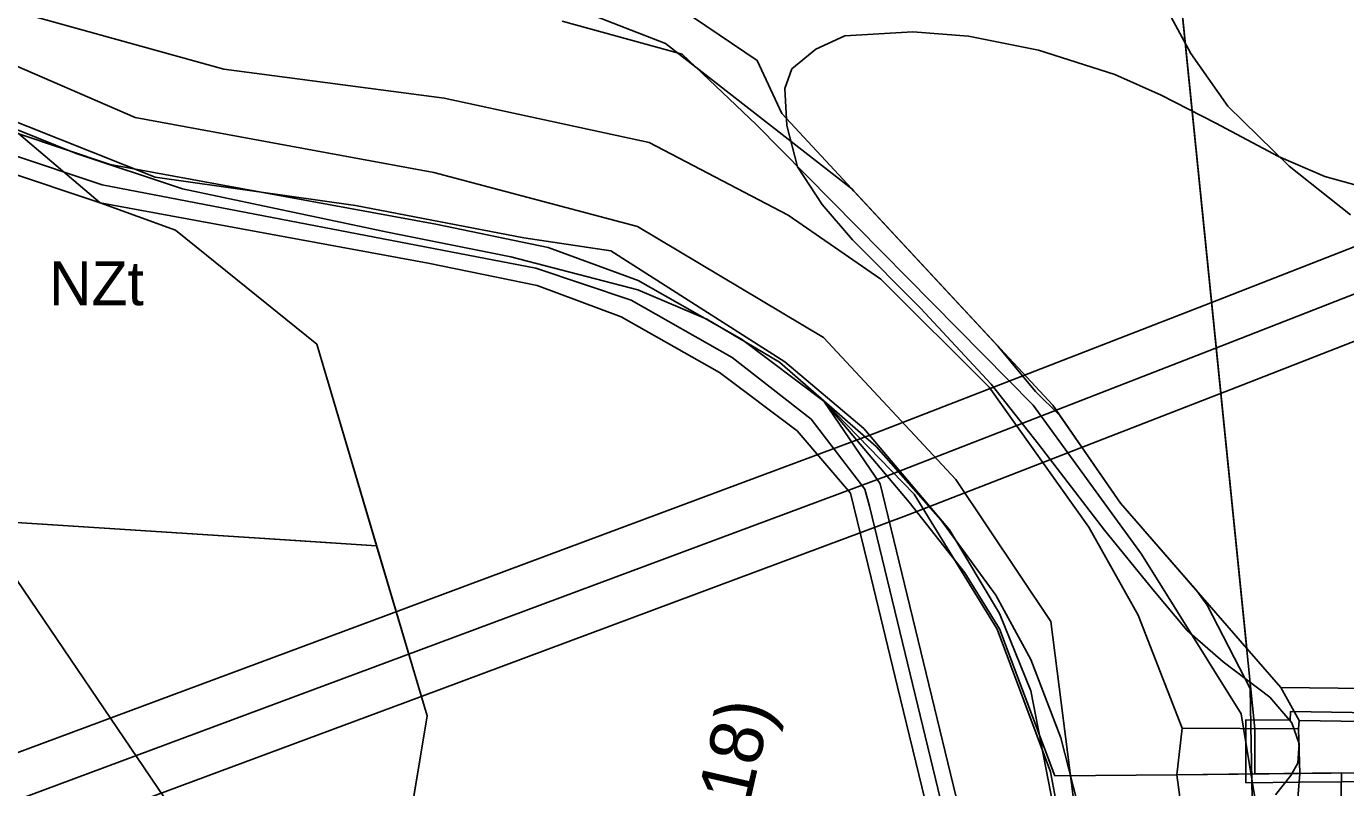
# Model space of a CAD drawing. Extents: x -758499 to -754160, y -1175205 to -1172032.
# Drawn here: x -756363 to -756063.4, y -1173393.7 to -1173220.7 of the extents above; entities that cross this region are included whole.
import ezdxf

# ---------------------------------------------------------------- set-up
doc = ezdxf.new("R2010")
doc.units = 0
for name, color, linetype in [('A012_RegLidArch_p', 7, 'Continuous'), ('A041_BPEJ_p', 7, 'Continuous'), ('A043_InvPuda_p', 7, 'Continuous'), ('A073_ElVed_l_VN', 7, 'Continuous'), ('A073_ElVed_op', 7, 'Continuous'), ('D cyklocesty NÁVRH', 7, 'Continuous'), ('HRANICE změn v krajině', 7, 'Continuous'), ('indexy RZV_TYP_1', 7, 'Continuous'), ('NÁVRH NZt zeměděl-trvalý travní porost', 7, 'Continuous'), ('PLOCHY NS smíšené nezastavěného území', 7, 'Continuous'), ('PLOCHY NZo zemědělské-orná půda', 7, 'Continuous'), ('PLOCHY NZt zeměděl-trvalý travní porost', 7, 'Continuous'), ('PLOCHY PV prostranství veřejné', 7, 'Continuous'), ('PLOCHY VV vodní a vodohospodářské', 7, 'Continuous'), ('vrstevnice', 7, 'Continuous'), ('ÚSES interakční prvek', 7, 'Continuous'), ('ÚSES LBC jako součást RBK', 7, 'Continuous'), ('ÚSES NBK funkční', 7, 'Continuous')]:
    doc.layers.add(name, color=color, linetype=linetype)

msp = doc.modelspace()

# ---------------------------------------------------------------- linework, layer by layer
at = {"layer": 'A012_RegLidArch_p'}
for p, q in [((-756394.8, -1173216.86), (-756338.3, -1173241.39)), ((-756338.3, -1173241.39), (-756270.44, -1173253.88)), ((-756270.44, -1173253.88), (-756224.2, -1173266.16)), ((-756224.2, -1173266.16), (-756182, -1173291.38)), ((-756182, -1173291.38), (-756151.93, -1173323.65)), ((-756151.93, -1173323.65), (-756130.31, -1173355.91)), ((-756130.31, -1173355.91), (-756120.85, -1173430.13))]:
    msp.add_line(p, q, dxfattribs=at)
at = {"layer": 'A041_BPEJ_p'}
for p, q in [((-756109.47, -1173206.48), (-756098.56, -1173226.87)), ((-756098.56, -1173226.87), (-756109.47, -1173206.48)), ((-756241.66, -1173215.35), (-756217.82, -1173224.56)), ((-756217.82, -1173224.56), (-756241.66, -1173215.35)), ((-756217.82, -1173224.56), (-756175.55, -1173257.62)), ((-756175.55, -1173257.62), (-756217.82, -1173224.56)), ((-756098.56, -1173226.87), (-756090.14, -1173238.78)), ((-756090.14, -1173238.78), (-756098.56, -1173226.87)), ((-756393.93, -1173231.07), (-756333.78, -1173254.91)), ((-756333.78, -1173254.91), (-756393.93, -1173231.07)), ((-756090.14, -1173238.78), (-756076.22, -1173252.42)), ((-756076.22, -1173252.42), (-756090.14, -1173238.78)), ((-756076.22, -1173252.42), (-756062.29, -1173263.52)), ((-756062.29, -1173263.52), (-756076.22, -1173252.42)), ((-756333.78, -1173254.91), (-756288.27, -1173261.41)), ((-756288.27, -1173261.41), (-756333.78, -1173254.91)), ((-756175.55, -1173257.62), (-756175.06, -1173258.13)), ((-756175.06, -1173258.13), (-756175.55, -1173257.62)), ((-756175.06, -1173258.13), (-756142.26, -1173293.45)), ((-756142.26, -1173293.45), (-756175.06, -1173258.13)), ((-756288.27, -1173261.41), (-756250, -1173268.73)), ((-756250, -1173268.73), (-756288.27, -1173261.41)), ((-756250, -1173268.73), (-756230.28, -1173271.71)), ((-756230.28, -1173271.71), (-756250, -1173268.73)), ((-756230.28, -1173271.71), (-756190.73, -1173296.9)), ((-756190.73, -1173296.9), (-756230.28, -1173271.71)), ((-756142.26, -1173293.45), (-756133.83, -1173303.68)), ((-756133.83, -1173303.68), (-756142.26, -1173293.45)), ((-756190.73, -1173296.9), (-756172.84, -1173312.08)), ((-756172.84, -1173312.08), (-756190.73, -1173296.9)), ((-756133.83, -1173303.68), (-756128.27, -1173309.11)), ((-756128.27, -1173309.11), (-756133.83, -1173303.68)), ((-756128.27, -1173309.11), (-756114.52, -1173329.01)), ((-756114.52, -1173329.01), (-756128.27, -1173309.11)), ((-756172.84, -1173312.08), (-756153.34, -1173335.11)), ((-756153.34, -1173335.11), (-756172.84, -1173312.08)), ((-756114.52, -1173329.01), (-756097.16, -1173348.97)), ((-756097.16, -1173348.97), (-756114.52, -1173329.01)), ((-756153.34, -1173335.11), (-756141.96, -1173354.07)), ((-756141.96, -1173354.07), (-756153.34, -1173335.11)), ((-756097.16, -1173348.97), (-756094.81, -1173352.18)), ((-756094.81, -1173352.18), (-756097.16, -1173348.97)), ((-756094.81, -1173352.18), (-756085.06, -1173371.14)), ((-756085.06, -1173371.14), (-756094.81, -1173352.18)), ((-756141.96, -1173354.07), (-756134.91, -1173371.68)), ((-756134.91, -1173371.68), (-756141.96, -1173354.07)), ((-756134.91, -1173371.68), (-756127.05, -1173411.78)), ((-756127.05, -1173411.78), (-756134.91, -1173371.68)), ((-756085.06, -1173371.14), (-756083.97, -1173428.85)), ((-756083.97, -1173428.85), (-756085.06, -1173371.14))]:
    msp.add_line(p, q, dxfattribs=at)
at = {"layer": 'A043_InvPuda_p'}
msp.add_line((-756482.65, -1173173.48), (-756302.97, -1173438.22), dxfattribs=at)
at = {"layer": 'A073_ElVed_l_VN'}
msp.add_lwpolyline([(-755889.67, -1173214.41), (-755997.14, -1173256.36), (-756090.37, -1173292.81), (-756166.71, -1173322.49), (-756277.23, -1173363.71), (-756391.79, -1173406.32), (-756503.08, -1173447.76), (-756614.81, -1173489.45), (-756725.9, -1173530.87), (-756829.91, -1173569.83)], dxfattribs=at)
at = {"layer": 'A073_ElVed_op'}
for points in [[(-756937.08, -1173599.18), (-756833.41, -1173560.46), (-756729.4, -1173521.5), (-756618.3, -1173480.08), (-756506.57, -1173438.39), (-756395.28, -1173396.95), (-756280.72, -1173354.34), (-756170.27, -1173313.14), (-756094, -1173283.49), (-756000.78, -1173247.05), (-755893.3, -1173205.09), (-755782.45, -1173161.86), (-755672.55, -1173119.02), (-755584.87, -1173084.82), (-755525.32, -1173086.94), (-755455.27, -1173089.86)], [(-755445.09, -1173111.7), (-755451.32, -1173110.05), (-755526.1, -1173106.92), (-755581.45, -1173104.96), (-755665.29, -1173137.66), (-755775.19, -1173180.5), (-755886.04, -1173223.73), (-755993.5, -1173265.67), (-756086.74, -1173302.13), (-756163.15, -1173331.84), (-756273.74, -1173373.08), (-756388.3, -1173415.69), (-756499.59, -1173457.13), (-756611.32, -1173498.82), (-756722.4, -1173540.24), (-756826.41, -1173579.2), (-756944.42, -1173623.27), (-756946.15, -1173623.58)]]:
    msp.add_lwpolyline(points, dxfattribs=at)
at = {"layer": 'D cyklocesty NÁVRH'}
for points in [[(-756433.17, -1173211.78), (-756414.04, -1173225.98), (-756390.12, -1173239.24), (-756366.64, -1173249.68), (-756345.77, -1173256.71), (-756247.28, -1173275.63), (-756225.64, -1173282.91), (-756202.74, -1173295.95), (-756184.77, -1173309.94), (-756172.56, -1173325.85), (-756171.51, -1173329.73), (-756155.38, -1173396.37), (-756155.96, -1173403.47), (-756162.92, -1173417.39), (-756161.76, -1173444.93), (-756154.08, -1173473.63), (-756147.12, -1173494.06), (-756148.28, -1173501.6), (-756152.48, -1173511.53), (-756169.15, -1173538.78), (-756182.2, -1173559.07), (-756209.01, -1173591.54), (-756236.26, -1173624.44)], [(-756249.6, -1173995.8), (-756304.39, -1173806.64), (-756305.26, -1173790.41), (-756304.1, -1173771.42), (-756294.53, -1173742.29), (-756274.67, -1173711.7), (-756265.69, -1173702.57), (-756213.5, -1173657.2), (-756173.79, -1173608.93), (-756149, -1173575.45), (-756123.93, -1173539.07), (-756113.78, -1173523.85), (-756096.39, -1173481.53), (-756089.28, -1173456.16), (-756083.34, -1173400.06), (-756087.11, -1173376.87), (-756109.72, -1173340.64), (-756134.36, -1173306.72), (-756197.27, -1173242.94), (-756214.08, -1173227), (-756241.33, -1173219.46)]]:
    msp.add_lwpolyline(points, dxfattribs=at)
at = {"layer": 'HRANICE změn v krajině'}
for points in [[(-756109.32, -1173130.91), (-756085.79, -1173362.04), (-756114.52, -1173329.01), (-756129.9, -1173306.76), (-756191.42, -1173240.51), (-756197.01, -1173228.43), (-756211.53, -1173218.65)], [(-756295.76, -1173521.24), (-756272, -1173377.37), (-756283.48, -1173338.71), (-756297.08, -1173292.89), (-756329.16, -1173266.98), (-756346.27, -1173260.76), (-756271.77, -1173274.48), (-756247.02, -1173279.58), (-756227.9, -1173286.65), (-756205.57, -1173299.31), (-756187.95, -1173312.56), (-756175.8, -1173326.75), (-756171.13, -1173345.99), (-756165.13, -1173370.73), (-756158.94, -1173396.25)]]:
    msp.add_lwpolyline(points, dxfattribs=at)
at = {"layer": 'NÁVRH NZt zeměděl-trvalý travní porost'}
for points in [[(-756109.32, -1173130.91), (-756085.79, -1173362.04), (-756114.52, -1173329.01), (-756129.9, -1173306.76), (-756191.42, -1173240.51), (-756197.01, -1173228.43), (-756211.53, -1173218.65)], [(-756295.76, -1173521.24), (-756272, -1173377.37), (-756283.48, -1173338.71), (-756297.08, -1173292.89), (-756329.16, -1173266.98), (-756346.27, -1173260.76), (-756271.77, -1173274.48), (-756247.02, -1173279.58), (-756227.9, -1173286.65), (-756205.57, -1173299.31), (-756187.95, -1173312.56), (-756175.8, -1173326.75), (-756171.13, -1173345.99), (-756165.13, -1173370.73), (-756158.94, -1173396.25)]]:
    msp.add_lwpolyline(points, dxfattribs=at)
at = {"layer": 'PLOCHY NS smíšené nezastavěného území'}
for points in [[(-756181.93, -1173305.82), (-756161.35, -1173326.95), (-756142.53, -1173357.66), (-756130.38, -1173390.03), (-756127.49, -1173405.81), (-756127.1, -1173440.75), (-756132.49, -1173472.62), (-756141.86, -1173497.39), (-756150.45, -1173474.34), (-756158.33, -1173444.24), (-756159.88, -1173418.2), (-756150.62, -1173400.84), (-756169.11, -1173324.64)], [(-756078.11, -1173370.87), (-755954.66, -1173372.32), (-755894.6, -1173371.63), (-755787.2, -1173371.96), (-755762.88, -1173369.67), (-755764.66, -1173377.87), (-755786.84, -1173379.96), (-755894.57, -1173379.63), (-755954.68, -1173380.32), (-756073.97, -1173378.42)], [(-756073.75, -1173390.42), (-755952.64, -1173389.17), (-755765.3, -1173388.97), (-755768.56, -1173394.97), (-755781.33, -1173395.88), (-755908.85, -1173395.64), (-755955.98, -1173396.49), (-756056.15, -1173398.03), (-756074.52, -1173399.82)]]:
    msp.add_lwpolyline(points, close=True, dxfattribs=at)
at = {"layer": 'PLOCHY NZo zemědělské-orná půda'}
for points in [[(-755723.48, -1173177.46), (-755733.96, -1173231.89), (-755736.18, -1173243.56), (-755741.53, -1173271.48), (-755752.03, -1173322.1), (-755758.93, -1173351.52), (-755762.88, -1173369.67), (-755787.2, -1173371.96), (-755894.6, -1173371.63), (-755954.66, -1173372.32), (-756078.11, -1173370.87), (-756085.79, -1173362.04), (-756109.32, -1173130.91)], [(-756439.98, -1173212.39), (-756430.37, -1173222.44), (-756432.3, -1173329.06), (-756311.31, -1173336.9), (-756283.48, -1173338.71), (-756272, -1173377.37), (-756295.76, -1173521.24), (-756415.28, -1173701.51), (-756445.99, -1173697.96)]]:
    msp.add_lwpolyline(points, dxfattribs=at)
at = {"layer": 'PLOCHY NZt zeměděl-trvalý travní porost'}
msp.add_lwpolyline([(-756430.37, -1173222.44), (-756393.84, -1173242.18), (-756367.97, -1173253.52), (-756346.27, -1173260.76), (-756329.16, -1173266.98), (-756297.08, -1173292.89), (-756283.48, -1173338.71), (-756301.79, -1173337.52), (-756432.3, -1173329.06)], close=True, dxfattribs=at)
at = {"layer": 'PLOCHY PV prostranství veřejné'}
for points in [[(-756431.99, -1173205.34), (-756410.68, -1173222.17), (-756389.79, -1173234.13), (-756364.73, -1173245.11), (-756344.01, -1173252.03), (-756270.03, -1173265.65), (-756244.54, -1173270.9), (-756224.09, -1173278.46), (-756200.63, -1173291.77), (-756181.93, -1173305.82), (-756169.11, -1173324.64), (-756150.62, -1173400.84), (-756159.88, -1173418.2), (-756158.33, -1173444.24), (-756150.45, -1173474.34), (-756141.86, -1173497.39), (-756147.33, -1173511.86), (-756162.75, -1173537.64), (-756179.25, -1173561.6), (-756230.21, -1173624.17)], [(-756186.03, -1173617.26), (-756154.47, -1173576.88), (-756124.17, -1173530.32), (-756102.4, -1173480.43), (-756095.07, -1173440.21), (-756101.73, -1173390.71), (-756100.52, -1173380.14), (-756110.53, -1173354.47), (-756121.7, -1173334.5), (-756144.32, -1173302.68), (-756168.97, -1173278.14), (-756189.98, -1173263.61), (-756221.55, -1173247.09), (-756268.16, -1173236.96), (-756318.17, -1173230.4), (-756361.3, -1173218.47)], [(-756211.53, -1173218.65), (-756197.01, -1173228.43), (-756191.42, -1173240.51), (-756129.9, -1173306.76), (-756114.52, -1173329.01), (-756085.79, -1173362.04), (-756078.11, -1173370.87), (-756073.97, -1173378.42), (-756074.05, -1173380.33), (-756073.75, -1173390.42), (-756074.52, -1173399.82), (-756076.18, -1173420.2), (-756079.36, -1173438.71), (-756082.5, -1173461.83), (-756089.32, -1173477.45), (-756108.45, -1173524.92), (-756130.83, -1173556.6), (-756150.28, -1173583.99), (-756171.25, -1173613.25)], [(-756237.88, -1173619.03), (-756186.45, -1173556.18), (-756173.72, -1173537.71), (-756155.37, -1173507.77), (-756152.11, -1173499.41), (-756152.02, -1173490.19), (-756157.13, -1173476.45), (-756161.1, -1173461.28), (-756165.28, -1173445.35), (-756166.98, -1173416.65), (-756159.68, -1173402.95), (-756158.94, -1173396.25), (-756165.13, -1173370.73), (-756171.13, -1173345.99), (-756175.8, -1173326.75), (-756187.95, -1173312.56), (-756205.57, -1173299.31), (-756227.9, -1173286.65), (-756247.02, -1173279.58), (-756271.77, -1173274.48), (-756346.27, -1173260.76), (-756367.97, -1173253.52)]]:
    msp.add_lwpolyline(points, dxfattribs=at)
at = {"layer": 'PLOCHY VV vodní a vodohospodářské'}
for points in [[(-756230.21, -1173624.17), (-756179.25, -1173561.6), (-756162.75, -1173537.64), (-756147.33, -1173511.86), (-756141.86, -1173497.39), (-756132.49, -1173472.62), (-756127.1, -1173440.75), (-756127.49, -1173405.81), (-756130.38, -1173390.03), (-756142.53, -1173357.66), (-756161.35, -1173326.95), (-756181.93, -1173305.82), (-756200.63, -1173291.77), (-756224.09, -1173278.46), (-756244.54, -1173270.9), (-756270.03, -1173265.65), (-756344.01, -1173252.03), (-756364.73, -1173245.11), (-756389.79, -1173234.13), (-756410.68, -1173222.17), (-756431.99, -1173205.34)], [(-756361.3, -1173218.47), (-756318.17, -1173230.4), (-756268.16, -1173236.96), (-756221.55, -1173247.09), (-756189.98, -1173263.61), (-756168.97, -1173278.14), (-756144.32, -1173302.68), (-756121.7, -1173334.5), (-756110.53, -1173354.47), (-756100.52, -1173380.14), (-756101.73, -1173390.71), (-756095.07, -1173440.21), (-756102.4, -1173480.43), (-756124.17, -1173530.32), (-756154.47, -1173576.88), (-756186.03, -1173617.26)]]:
    msp.add_lwpolyline(points, dxfattribs=at)
msp.add_lwpolyline([(-756100.52, -1173380.14), (-756074.05, -1173380.33), (-756073.97, -1173378.42), (-755954.68, -1173380.32), (-755894.57, -1173379.63), (-755786.84, -1173379.96), (-755764.66, -1173377.87), (-755763.8, -1173381.67), (-755764.78, -1173387.08), (-755765.3, -1173388.97), (-755952.64, -1173389.17), (-756073.75, -1173390.42), (-756101.73, -1173390.71)], close=True, dxfattribs=at)
at = {"layer": 'vrstevnice'}
for p, q in [((-756183.69, -1173225.86), (-756177.09, -1173222.85)), ((-756177.09, -1173222.85), (-756161.7, -1173221.94)), ((-756161.7, -1173221.94), (-756149, -1173222.93)), ((-756149, -1173222.93), (-756133.15, -1173226.09)), ((-756189.16, -1173230.33), (-756183.69, -1173225.86)), ((-756133.15, -1173226.09), (-756115.81, -1173231.62)), ((-756190.78, -1173234.76), (-756189.16, -1173230.33)), ((-756115.81, -1173231.62), (-756105.28, -1173236.31)), ((-756190.33, -1173243.21), (-756190.78, -1173234.76)), ((-756105.28, -1173236.31), (-756092.87, -1173242.68)), ((-756351.69, -1173249.55), (-756373.11, -1173240.93)), ((-756187.85, -1173252.57), (-756190.33, -1173243.21)), ((-756092.87, -1173242.68), (-756078.63, -1173250.27)), ((-756327.52, -1173257.6), (-756351.69, -1173249.55)), ((-756078.63, -1173250.27), (-756068.1, -1173254.77)), ((-756182.25, -1173261.16), (-756187.85, -1173252.57)), ((-756068.1, -1173254.77), (-756057.96, -1173257.61)), ((-756280.97, -1173267.46), (-756327.52, -1173257.6)), ((-756175.36, -1173269.19), (-756182.25, -1173261.16)), ((-756252.95, -1173273.08), (-756280.97, -1173267.46)), ((-756159.95, -1173284.68), (-756175.36, -1173269.19)), ((-756224.13, -1173280.58), (-756252.95, -1173273.08)), ((-756208.43, -1173287.24), (-756224.13, -1173280.58)), ((-756143.91, -1173301.95), (-756159.95, -1173284.68)), ((-756191.97, -1173297.01), (-756208.43, -1173287.24)), ((-756170, -1173316.17), (-756191.97, -1173297.01)), ((-756133.11, -1173315.64), (-756143.91, -1173301.95)), ((-756155.31, -1173332.77), (-756170, -1173316.17)), ((-756118.14, -1173335.16), (-756133.11, -1173315.64)), ((-756142.83, -1173349.94), (-756155.31, -1173332.77)), ((-756107.16, -1173348.67), (-756118.14, -1173335.16)), ((-756099.35, -1173357.98), (-756107.16, -1173348.67)), ((-756134.88, -1173364.56), (-756142.83, -1173349.94)), ((-756091.19, -1173365.07), (-756099.35, -1173357.98)), ((-756128.09, -1173382.33), (-756134.88, -1173364.56)), ((-756080.63, -1173373.07), (-756091.19, -1173365.07)), ((-756075.6, -1173378.91), (-756080.63, -1173373.07)), ((-756073.9, -1173383.67), (-756075.6, -1173378.91)), ((-756123.12, -1173401.6), (-756128.09, -1173382.33)), ((-756074.23, -1173388.09), (-756073.9, -1173383.67)), ((-756075.86, -1173390.86), (-756074.23, -1173388.09)), ((-756079.31, -1173395.31), (-756075.86, -1173390.86))]:
    msp.add_line(p, q, dxfattribs=at)
at = {"layer": 'ÚSES interakční prvek'}
msp.add_lwpolyline([(-756064.26, -1173392.32), (-756073.73, -1173392.42), (-756086.01, -1173392.55), (-756086.02, -1173378.24), (-756075.97, -1173378.32), (-756075.89, -1173376.39), (-755954.68, -1173378.32), (-755894.58, -1173377.63), (-755786.93, -1173377.96), (-755763.1, -1173375.71), (-755761.76, -1173381.63), (-755762.83, -1173387.52), (-755763.78, -1173390.97), (-755952.63, -1173391.17)], close=True, dxfattribs=at)
at = {"layer": 'ÚSES LBC jako součást RBK'}
for p, q in [((-756084.02, -1173380.26), (-756109.32, -1173130.91)), ((-756162.53, -1173328.78), (-756149.88, -1173344.83)), ((-756149.88, -1173344.83), (-756141.97, -1173357.58)), ((-756141.97, -1173357.58), (-756129.43, -1173391.01)), ((-756084.01, -1173390.53), (-756084.02, -1173380.26)), ((-756129.43, -1173391.01), (-756101.73, -1173390.71)), ((-756101.73, -1173390.71), (-756084.01, -1173390.53))]:
    msp.add_line(p, q, dxfattribs=at)
msp.add_lwpolyline([(-756364.73, -1173245.11), (-756344.01, -1173252.03), (-756270.03, -1173265.65), (-756244.54, -1173270.9), (-756224.09, -1173278.46), (-756200.63, -1173291.77), (-756181.93, -1173305.82), (-756162.53, -1173328.78)], dxfattribs=at)
at = {"layer": 'ÚSES NBK funkční'}
for points in [[(-756461.07, -1173173.02), (-756431.99, -1173205.34), (-756410.68, -1173222.17), (-756389.79, -1173234.13), (-756364.73, -1173245.11), (-756346.27, -1173260.76), (-756329.16, -1173266.98), (-756297.08, -1173292.89), (-756272, -1173377.37), (-756295.83, -1173521.09), (-756378.92, -1173717.91), (-756380.25, -1173725.67), (-756470.53, -1173787.35)], [(-756270.58, -1173942.76), (-756262.48, -1173934.3), (-756077.06, -1173478.96), (-756067.81, -1173452.32), (-756066.69, -1173440.28), (-756064.93, -1173421.23), (-756064.28, -1173390.32), (-756084.01, -1173390.53)]]:
    msp.add_lwpolyline(points, dxfattribs=at)

# ---------------------------------------------------------------- texts
at = {"layer": 'indexy RZV_TYP_1'}
msp.add_text('NZt', height=10, dxfattribs=at).set_placement((-756357.86, -1173284.05))
at = {"layer": 'ÚSES NBK funkční'}
msp.add_text('(Červené blato-K118)', height=12, rotation=77.0912, dxfattribs=at).set_placement((-756227.93, -1173524.7))

doc.saveas('drawing.dxf')
